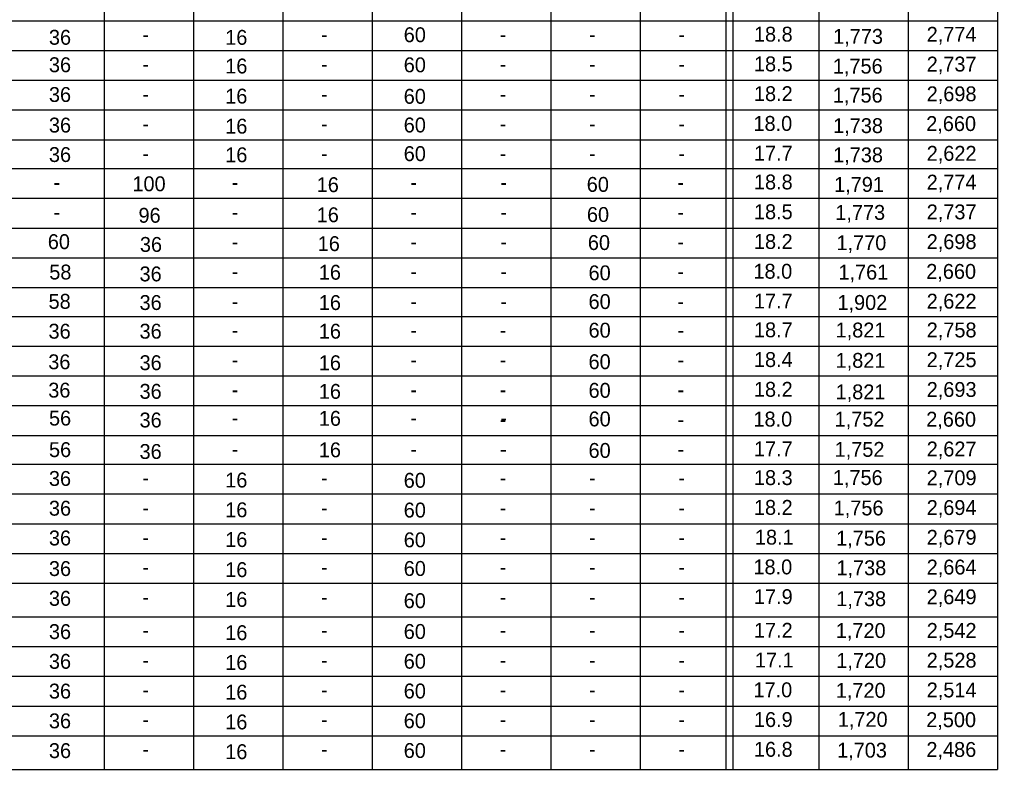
# Model space of a CAD drawing. Extents: x -50.5 to -14.4, y -5.1 to 16.9.
# Drawn here: x -45.7 to -37.49, y 4.12 to 10.42 of the extents above; entities that cross this region are included whole.
import ezdxf

# ---------------------------------------------------------------- set-up
doc = ezdxf.new("R2010")
doc.units = 0
for name, color, linetype in [('BR_BORDER LINES', 7, 'Continuous'), ('BR_TABLE LINES', 7, 'Continuous'), ('BR_TEXT', 7, 'Continuous')]:
    doc.layers.add(name, color=color, linetype=linetype)

msp = doc.modelspace()

# ---------------------------------------------------------------- linework, layer by layer
at = {"layer": 'BR_BORDER LINES'}
for p in [(-37.4943, 16.4338), (-48.6853, 4.1202)]:
    msp.add_line(p, (-37.4943, 4.1202), dxfattribs=at)
at = {"layer": 'BR_TABLE LINES'}
for p, q in [((-44.9943, 15.7748), (-44.9943, 4.1202)), ((-44.2443, 15.7748), (-44.2443, 4.1202)), ((-43.4943, 15.7748), (-43.4943, 4.1202)), ((-42.7443, 15.7748), (-42.7443, 4.1202)), ((-41.9943, 15.7748), (-41.9943, 4.1202)), ((-41.2443, 15.7748), (-41.2443, 4.1202)), ((-40.4943, 15.7748), (-40.4943, 4.1202)), ((-39.7733, 15.7748), (-39.7733, 4.1202)), ((-39.7152, 15.7748), (-39.7152, 4.1202)), ((-38.9943, 15.7748), (-38.9943, 4.1202)), ((-38.2443, 15.7748), (-38.2443, 4.1202)), ((-48.6853, 10.4107), (-37.4943, 10.4107)), ((-47.233, 10.1607), (-37.4943, 10.1607)), ((-47.233, 9.9107), (-37.4943, 9.9107)), ((-47.233, 9.6607), (-37.4943, 9.6607)), ((-47.233, 9.4107), (-37.4943, 9.4107)), ((-48.6853, 9.1687), (-37.4943, 9.1687)), ((-47.233, 8.9187), (-37.4943, 8.9187)), ((-47.233, 8.6687), (-37.4943, 8.6687)), ((-47.233, 8.4187), (-37.4943, 8.4187)), ((-47.233, 8.1687), (-37.4943, 8.1687)), ((-48.0649, 7.9268), (-37.4943, 7.9268)), ((-47.233, 7.6768), (-37.4943, 7.6768)), ((-47.233, 7.4268), (-37.4943, 7.4268)), ((-47.233, 7.1768), (-37.4943, 7.1768)), ((-47.233, 6.9268), (-37.4943, 6.9268)), ((-48.0649, 6.6849), (-37.4943, 6.6849)), ((-47.233, 6.4349), (-37.4943, 6.4349)), ((-47.233, 6.1849), (-37.4943, 6.1849)), ((-47.233, 5.9349), (-37.4943, 5.9349)), ((-47.233, 5.6849), (-37.4943, 5.6849)), ((-48.0649, 5.4026), (-37.4943, 5.4026)), ((-47.233, 5.1526), (-37.4943, 5.1526)), ((-47.233, 4.9026), (-37.4943, 4.9026)), ((-47.233, 4.6526), (-37.4943, 4.6526)), ((-47.233, 4.4026), (-37.4943, 4.4026))]:
    msp.add_line(p, q, dxfattribs=at)

# ---------------------------------------------------------------- texts
at = {"layer": 'BR_TEXT'}
for s, p in [('60', (-42.4786, 10.23)), ('18.8', (-39.5386, 10.235)), ('2,774', (-38.0882, 10.2337)), ('36', (-45.4572, 10.2086)), ('-', (-44.6732, 10.2323)), ('16', (-43.977, 10.208)), ('-', (-43.1732, 10.2323)), ('-', (-41.6732, 10.2323)), ('-', (-40.9232, 10.2323)), ('-', (-40.1732, 10.2323)), ('1,773', (-38.8736, 10.2163)), ('36', (-45.4572, 9.978)), ('60', (-42.4786, 9.9773)), ('18.5', (-39.5386, 9.985)), ('2,737', (-38.0882, 9.9837)), ('-', (-44.6732, 9.9823)), ('16', (-43.977, 9.9674)), ('-', (-43.1732, 9.9823)), ('-', (-41.6732, 9.9823)), ('-', (-40.9232, 9.9823)), ('-', (-40.1732, 9.9823)), ('1,756', (-38.876, 9.9663)), ('36', (-45.4572, 9.728)), ('18.2', (-39.5386, 9.735)), ('2,698', (-38.0882, 9.7337)), ('-', (-44.6732, 9.7323)), ('16', (-43.977, 9.7147)), ('-', (-43.1732, 9.7323)), ('60', (-42.4786, 9.7126)), ('-', (-41.6732, 9.7323)), ('-', (-40.9232, 9.7323)), ('-', (-40.1732, 9.7323)), ('1,756', (-38.876, 9.7227)), ('18.0', (-39.5425, 9.485)), ('2,660', (-38.0921, 9.4837)), ('36', (-45.4572, 9.4711)), ('-', (-44.6732, 9.4823)), ('16', (-43.977, 9.462)), ('-', (-43.1732, 9.4823)), ('60', (-42.4786, 9.472)), ('-', (-41.6732, 9.4823)), ('-', (-40.9232, 9.4823)), ('-', (-40.1732, 9.4823)), ('1,738', (-38.8736, 9.4663)), ('17.7', (-39.5386, 9.235)), ('2,622', (-38.0882, 9.2337)), ('36', (-45.4572, 9.2236)), ('-', (-44.6732, 9.2323)), ('16', (-43.977, 9.2214)), ('-', (-43.1732, 9.2323)), ('60', (-42.4786, 9.2313)), ('-', (-41.6732, 9.2323)), ('-', (-40.9232, 9.2323)), ('-', (-40.1732, 9.2323)), ('1,738', (-38.8736, 9.2208)), ('18.8', (-39.5386, 8.9931)), ('2,774', (-38.0882, 8.9918)), ('-', (-45.4189, 8.9904)), ('100', (-44.7562, 8.9779)), ('-', (-43.9232, 8.9904)), ('16', (-43.2091, 8.9705)), ('-', (-42.4232, 8.9904)), ('-', (-41.667, 8.9904)), ('60', (-40.9421, 8.9727)), ('-', (-40.1811, 8.9904)), ('1,791', (-38.8654, 8.9727)), ('18.5', (-39.5386, 8.7431)), ('2,737', (-38.0882, 8.7418)), ('-', (-45.4189, 8.7404)), ('96', (-44.705, 8.7132)), ('-', (-43.9232, 8.7404)), ('16', (-43.2091, 8.7176)), ('-', (-42.4232, 8.7404)), ('-', (-41.667, 8.7404)), ('60', (-40.9406, 8.7198)), ('-', (-40.1811, 8.7404)), ('1,773', (-38.8554, 8.7373)), ('18.2', (-39.5386, 8.4931)), ('60', (-45.4665, 8.4919)), ('36', (-44.6934, 8.4683)), ('-', (-43.9232, 8.4904)), ('16', (-43.2005, 8.4752)), ('-', (-42.4232, 8.4904)), ('-', (-41.667, 8.4904)), ('60', (-40.9327, 8.4841)), ('-', (-40.1811, 8.4904)), ('1,770', (-38.8456, 8.4829)), ('2,698', (-38.0882, 8.4918)), ('58', (-45.4542, 8.2366)), ('36', (-44.6964, 8.2208)), ('-', (-43.9232, 8.2404)), ('16', (-43.1915, 8.2346)), ('-', (-42.4232, 8.2404)), ('-', (-41.667, 8.2404)), ('60', (-40.927, 8.2297)), ('-', (-40.1811, 8.2404)), ('18.0', (-39.5425, 8.2431)), ('1,761', (-38.8292, 8.2354)), ('2,660', (-38.0921, 8.2418)), ('58', (-45.4602, 7.9904)), ('36', (-44.6964, 7.9802)), ('-', (-43.9232, 7.9904)), ('16', (-43.1915, 7.9799)), ('-', (-42.4232, 7.9904)), ('-', (-41.667, 7.9904)), ('60', (-40.927, 7.9885)), ('-', (-40.1811, 7.9904)), ('17.7', (-39.5386, 7.9931)), ('1,902', (-38.8375, 7.981)), ('2,622', (-38.0882, 7.9918)), ('36', (-45.4606, 7.7394)), ('36', (-44.6964, 7.7396)), ('-', (-43.9232, 7.7485)), ('16', (-43.1915, 7.7393)), ('-', (-42.4232, 7.7485)), ('-', (-41.6732, 7.7485)), ('60', (-40.927, 7.7479)), ('-', (-40.1805, 7.7485)), ('18.7', (-39.5386, 7.7512)), ('1,821', (-38.8528, 7.7493)), ('2,758', (-38.0882, 7.7499)), ('36', (-45.4626, 7.4824)), ('36', (-44.6964, 7.4749)), ('-', (-43.9232, 7.4985)), ('16', (-43.1915, 7.4746)), ('-', (-42.4232, 7.4985)), ('-', (-41.6732, 7.4985)), ('60', (-40.927, 7.4832)), ('-', (-40.1805, 7.4985)), ('18.4', (-39.5386, 7.5012)), ('1,821', (-38.8528, 7.4944)), ('2,725', (-38.0882, 7.4999)), ('36', (-45.4626, 7.2444)), ('36', (-44.6964, 7.2343)), ('16', (-43.1915, 7.234)), ('60', (-40.927, 7.2426)), ('18.2', (-39.5386, 7.2512)), ('1,821', (-38.8528, 7.2297)), ('2,693', (-38.0882, 7.2499)), ('-', (-43.9232, 7.2485)), ('-', (-42.4232, 7.2485)), ('-', (-41.6732, 7.2485)), ('-', (-40.1805, 7.2485)), ('56', (-45.4566, 7.0093)), ('36', (-44.6964, 6.9936)), ('-', (-43.9232, 7.0132)), ('16', (-43.1915, 7.0074)), ('-', (-42.4232, 7.0132)), ('-', (-41.667, 7.0132)), ('60', (-40.927, 7.0025)), ('18.0', (-39.5425, 7.0012)), ('1,752', (-38.8611, 7.0011)), ('2,660', (-38.0921, 6.9999)), ('-', (-41.6732, 6.9985)), ('-', (-40.1805, 6.9985)), ('56', (-45.4566, 6.7447)), ('36', (-44.6964, 6.7289)), ('16', (-43.1915, 6.7427)), ('60', (-40.927, 6.7378)), ('17.7', (-39.5386, 6.7512)), ('1,752', (-38.8611, 6.7467)), ('2,627', (-38.0882, 6.7499)), ('-', (-43.9232, 6.7485)), ('-', (-43.9232, 6.7485)), ('-', (-42.4232, 6.7485)), ('-', (-42.4232, 6.7485)), ('-', (-41.6732, 6.7485)), ('-', (-41.667, 6.7485)), ('-', (-40.1805, 6.7485)), ('36', (-45.4572, 6.5023)), ('16', (-43.977, 6.489)), ('60', (-42.4786, 6.4869)), ('18.3', (-39.5386, 6.5093)), ('1,756', (-38.876, 6.5096)), ('2,709', (-38.0882, 6.508)), ('-', (-44.6732, 6.5066)), ('-', (-43.1732, 6.5066)), ('-', (-41.6732, 6.5066)), ('-', (-40.9232, 6.5066)), ('-', (-40.1732, 6.5066)), ('36', (-45.4572, 6.2523)), ('16', (-43.977, 6.239)), ('60', (-42.4786, 6.2369)), ('18.2', (-39.5386, 6.2593)), ('1,756', (-38.8691, 6.2547)), ('2,694', (-38.0882, 6.258)), ('-', (-44.6732, 6.2566)), ('-', (-43.1732, 6.2566)), ('-', (-41.6732, 6.2566)), ('-', (-40.9232, 6.2566)), ('-', (-40.1732, 6.2566)), ('36', (-45.4572, 6.0023)), ('16', (-43.977, 5.989)), ('60', (-42.4786, 5.9869)), ('18.1', (-39.5303, 6.0093)), ('1,756', (-38.8485, 6.0004)), ('2,679', (-38.0882, 6.008)), ('-', (-44.6732, 6.0066)), ('-', (-43.1732, 6.0066)), ('-', (-41.6732, 6.0066)), ('-', (-40.9232, 6.0066)), ('-', (-40.1732, 6.0066)), ('36', (-45.4572, 5.7454)), ('16', (-43.977, 5.7363)), ('60', (-42.4786, 5.7462)), ('18.0', (-39.5425, 5.7593)), ('1,738', (-38.8461, 5.752)), ('2,664', (-38.0882, 5.758)), ('-', (-44.6732, 5.7566)), ('-', (-43.1732, 5.7566)), ('-', (-41.6732, 5.7566)), ('-', (-40.9232, 5.7566)), ('-', (-40.1732, 5.7566)), ('36', (-45.4572, 5.4954)), ('16', (-43.977, 5.4863)), ('60', (-42.4786, 5.4756)), ('17.9', (-39.5386, 5.5093)), ('1,738', (-38.8474, 5.4921)), ('2,649', (-38.0882, 5.508)), ('-', (-44.6732, 5.5066)), ('-', (-43.1732, 5.5066)), ('-', (-41.6732, 5.5066)), ('-', (-40.9232, 5.5066)), ('-', (-40.1732, 5.5066)), ('36', (-45.4572, 5.216)), ('60', (-42.4786, 5.2169)), ('17.2', (-39.5386, 5.2269)), ('1,720', (-38.8513, 5.2249)), ('2,542', (-38.0882, 5.2256)), ('-', (-44.6732, 5.2272)), ('16', (-43.977, 5.2069)), ('-', (-43.1732, 5.2272)), ('-', (-41.6732, 5.2272)), ('-', (-40.9232, 5.2272)), ('-', (-40.1732, 5.2272)), ('36', (-45.4572, 4.966)), ('60', (-42.4786, 4.9669)), ('17.1', (-39.5303, 4.9769)), ('1,720', (-38.8474, 4.9735)), ('2,528', (-38.0882, 4.9756)), ('-', (-44.6732, 4.9772)), ('16', (-43.977, 4.9569)), ('-', (-43.1732, 4.9772)), ('-', (-41.6732, 4.9772)), ('-', (-40.9232, 4.9772)), ('-', (-40.1732, 4.9772)), ('60', (-42.4786, 4.7169)), ('17.0', (-39.5425, 4.7269)), ('1,720', (-38.8513, 4.7221)), ('2,514', (-38.0882, 4.7256)), ('36', (-45.4572, 4.716)), ('-', (-44.6732, 4.7272)), ('16', (-43.977, 4.7069)), ('-', (-43.1732, 4.7272)), ('-', (-41.6732, 4.7272)), ('-', (-40.9232, 4.7272)), ('-', (-40.1732, 4.7272)), ('16.9', (-39.5386, 4.4769)), ('1,720', (-38.8345, 4.4785)), ('2,500', (-38.0921, 4.4756)), ('36', (-45.4572, 4.466)), ('-', (-44.6732, 4.4772)), ('16', (-43.977, 4.4569)), ('-', (-43.1732, 4.4772)), ('60', (-42.4786, 4.4669)), ('-', (-41.6732, 4.4772)), ('-', (-40.9232, 4.4772)), ('-', (-40.1732, 4.4772)), ('16.8', (-39.5386, 4.2269)), ('2,486', (-38.0906, 4.2256)), ('36', (-45.4572, 4.216)), ('-', (-44.6732, 4.2272)), ('16', (-43.977, 4.2069)), ('-', (-43.1732, 4.2272)), ('60', (-42.4786, 4.2169)), ('-', (-41.6732, 4.2272)), ('-', (-40.9232, 4.2272)), ('-', (-40.1732, 4.2272)), ('1,703', (-38.8406, 4.2196))]:
    msp.add_text(s, height=0.125, dxfattribs=at).set_placement(p)

doc.saveas('drawing.dxf')
